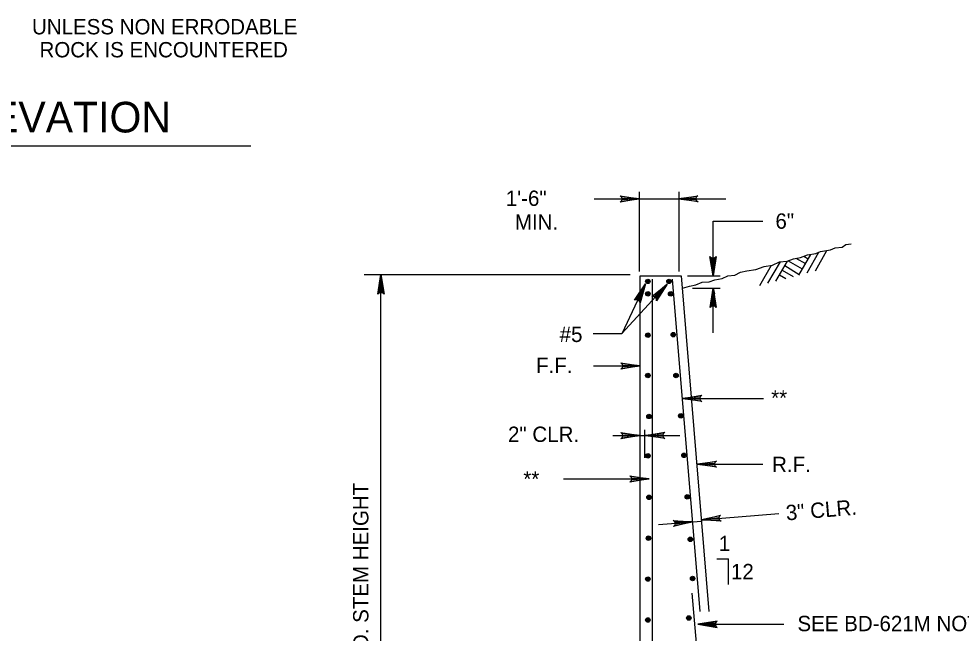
# Model space of a CAD drawing. Extents: x 639011 to 639866, y 298840 to 300028.
# Drawn here: x 639198.6 to 639383, y 299575.8 to 299696 of the extents above; entities that cross this region are included whole.
import ezdxf

# ---------------------------------------------------------------- set-up
doc = ezdxf.new("R2010")
doc.units = 0
doc.layers.add('2', color=7, linetype='Continuous')

msp = doc.modelspace()

# ---------------------------------------------------------------- linework, layer by layer
at = {"layer": '2'}
for p, q in [((639139.55, 299671.18), (639243.97, 299671.18)), ((639316.44, 299661.22), (639316.25, 299661.38)), ((639316.25, 299661.38), (639320.05, 299660.79)), ((639316.44, 299661.22), (639316.58, 299660.96)), ((639320.05, 299660.79), (639316.44, 299661.22)), ((639316.58, 299660.96), (639320.05, 299660.79)), ((639316.58, 299660.96), (639316.58, 299660.59)), ((639320.05, 299646.59), (639320.05, 299662.17)), ((639320.05, 299646.59), (639320.05, 299662.17)), ((639327.68, 299660.79), (639331.47, 299661.42)), ((639331.28, 299661.25), (639327.68, 299660.79)), ((639327.68, 299660.79), (639331.15, 299660.99)), ((639327.8, 299646.59), (639327.8, 299662.17)), ((639327.8, 299646.59), (639327.8, 299662.17)), ((639331.15, 299660.99), (639331.28, 299661.25)), ((639331.15, 299660.62), (639331.15, 299660.99)), ((639331.47, 299661.42), (639331.28, 299661.25)), ((639311.18, 299660.79), (639320.05, 299660.79)), ((639320.05, 299660.79), (639316.26, 299660.16)), ((639316.26, 299660.16), (639316.45, 299660.33)), ((639316.45, 299660.33), (639320.05, 299660.79)), ((639316.58, 299660.59), (639316.45, 299660.33)), ((639320.05, 299660.79), (639316.58, 299660.59)), ((639320.05, 299660.79), (639316.58, 299660.77)), ((639320.05, 299660.79), (639327.68, 299660.79)), ((639327.68, 299660.79), (639331.15, 299660.81)), ((639327.68, 299660.79), (639336.93, 299660.79)), ((639331.15, 299660.62), (639327.68, 299660.79)), ((639327.68, 299660.79), (639331.29, 299660.36)), ((639331.48, 299660.2), (639327.68, 299660.79)), ((639331.29, 299660.36), (639331.15, 299660.62)), ((639331.29, 299660.36), (639331.48, 299660.2)), ((639334.43, 299645.72), (639334.43, 299656.46)), ((639334.43, 299656.46), (639344.15, 299656.46)), ((639351.18, 299645.86), (639353.57, 299649.94)), ((639352.87, 299646.3), (639355.14, 299650.34)), ((639354.44, 299646.71), (639356.68, 299650.7)), ((639334.43, 299645.72), (639333.79, 299649.51)), ((639333.79, 299649.51), (639333.97, 299649.32)), ((639334.23, 299649.19), (639333.97, 299649.32)), ((639333.97, 299649.32), (639334.43, 299645.72)), ((639334.43, 299645.72), (639334.23, 299649.19)), ((639334.59, 299649.19), (639334.23, 299649.19)), ((639334.43, 299645.72), (639334.41, 299649.19)), ((639335.02, 299649.52), (639334.43, 299645.72)), ((639334.43, 299645.72), (639334.86, 299649.33)), ((639334.59, 299649.19), (639334.43, 299645.72)), ((639334.86, 299649.33), (639334.59, 299649.19)), ((639334.86, 299649.33), (639335.02, 299649.52)), ((639345.13, 299644.28), (639347.59, 299648.48)), ((639346.7, 299644.69), (639349.01, 299648.62)), ((639349.15, 299648.68), (639351.89, 299647.08)), ((639350.6, 299649.17), (639352.52, 299648.15)), ((639352.18, 299649.57), (639353.05, 299649.06)), ((639343.56, 299643.87), (639345.87, 299647.81)), ((639347.95, 299646.82), (639350.09, 299645.57)), ((639348.49, 299647.74), (639351.27, 299646.01)), ((639266.18, 299645.97), (639318.21, 299645.97)), ((639268.84, 299642.16), (639269.43, 299645.97)), ((639269.43, 299645.97), (639269, 299642.36)), ((639269.26, 299642.49), (639269.43, 299645.97)), ((639269.43, 299537.34), (639269.43, 299645.97)), ((639269.43, 299645.97), (639269.62, 299642.5)), ((639269.89, 299642.37), (639269.43, 299645.97)), ((639269.43, 299645.97), (639270.06, 299642.17)), ((639269.43, 299645.97), (639269.44, 299642.49)), ((639320.18, 299645.72), (639328.18, 299645.72)), ((639320.18, 299537.22), (639320.18, 299645.72)), ((639322.55, 299547.22), (639322.55, 299645.09)), ((639326.43, 299645.09), (639331.85, 299580.02)), ((639328.18, 299645.72), (639333.63, 299580)), ((639329.43, 299645.72), (639335.8, 299645.72)), ((639329.43, 299645.72), (639335.8, 299645.72)), ((639347.42, 299645.91), (639348.64, 299645.19)), ((639316.59, 299634.46), (639325.44, 299644.09)), ((639316.61, 299634.46), (639321.18, 299644.16)), ((639319.03, 299640.97), (639321.18, 299644.16)), ((639321.18, 299644.16), (639319.26, 299641.07)), ((639319.55, 299641.08), (639321.18, 299644.16)), ((639321.18, 299644.16), (639319.72, 299641.01)), ((639321.18, 299644.16), (639319.88, 299640.93)), ((639320.06, 299640.71), (639321.18, 299644.16)), ((639321.18, 299644.16), (639320.14, 299640.45)), ((639322.43, 299641.69), (639325.44, 299644.09)), ((639325.44, 299644.09), (639322.68, 299641.73)), ((639322.96, 299641.65), (639325.44, 299644.09)), ((639325.44, 299644.09), (639323.1, 299641.53)), ((639325.44, 299644.09), (639323.23, 299641.4)), ((639323.34, 299641.13), (639325.44, 299644.09)), ((639325.44, 299644.09), (639323.34, 299640.87)), ((639330.43, 299643.34), (639335.8, 299643.34)), ((639330.43, 299643.34), (639335.8, 299643.34)), ((639333.84, 299639.54), (639334.43, 299643.34)), ((639334.43, 299643.34), (639334, 299639.73)), ((639334.26, 299639.87), (639334.43, 299643.34)), ((639334.43, 299634.59), (639334.43, 299643.34)), ((639334.43, 299643.34), (639334.62, 299639.87)), ((639334.89, 299639.74), (639334.43, 299643.34)), ((639334.43, 299643.34), (639335.06, 299639.55)), ((639334.43, 299643.34), (639334.44, 299639.87)), ((639269, 299642.36), (639268.84, 299642.16)), ((639269, 299642.36), (639269.26, 299642.49)), ((639269.26, 299642.49), (639269.62, 299642.5)), ((639269.62, 299642.5), (639269.89, 299642.37)), ((639270.06, 299642.17), (639269.89, 299642.37)), ((639319.26, 299641.07), (639319.03, 299640.97)), ((639319.26, 299641.07), (639319.55, 299641.08)), ((639319.55, 299641.08), (639319.88, 299640.93)), ((639319.88, 299640.93), (639320.06, 299640.71)), ((639320.14, 299640.45), (639320.06, 299640.71)), ((639322.68, 299641.73), (639322.43, 299641.69)), ((639322.68, 299641.73), (639322.96, 299641.65)), ((639322.96, 299641.65), (639323.23, 299641.4)), ((639323.23, 299641.4), (639323.34, 299641.13)), ((639323.34, 299640.87), (639323.34, 299641.13)), ((639334, 299639.73), (639333.84, 299639.54)), ((639334, 299639.73), (639334.26, 299639.87)), ((639334.26, 299639.87), (639334.62, 299639.87)), ((639334.62, 299639.87), (639334.89, 299639.74)), ((639335.06, 299639.55), (639334.89, 299639.74)), ((639310.97, 299634.46), (639316.59, 299634.46)), ((639311.06, 299628.09), (639320.18, 299628.09)), ((639316.57, 299628.52), (639316.38, 299628.68)), ((639316.38, 299628.68), (639320.18, 299628.09)), ((639320.18, 299628.09), (639316.38, 299627.46)), ((639316.57, 299628.52), (639316.7, 299628.26)), ((639320.18, 299628.09), (639316.57, 299628.52)), ((639316.58, 299627.63), (639320.18, 299628.09)), ((639316.71, 299627.9), (639316.58, 299627.63)), ((639316.7, 299628.26), (639320.18, 299628.09)), ((639316.7, 299628.26), (639316.71, 299627.9)), ((639320.18, 299628.09), (639316.71, 299627.9)), ((639320.18, 299628.09), (639316.71, 299628.08)), ((639316.38, 299627.46), (639316.58, 299627.63)), ((639328.43, 299621.72), (639332.22, 299622.35)), ((639332.22, 299622.35), (639332.03, 299622.17)), ((639332.03, 299622.17), (639328.43, 299621.72)), ((639328.43, 299621.72), (639331.9, 299621.91)), ((639328.43, 299621.72), (639331.9, 299621.73)), ((639328.43, 299621.72), (639344.3, 299621.72)), ((639331.9, 299621.55), (639328.43, 299621.72)), ((639328.43, 299621.72), (639332.04, 299621.29)), ((639332.23, 299621.13), (639328.43, 299621.72)), ((639331.9, 299621.91), (639332.03, 299622.17)), ((639331.9, 299621.55), (639331.9, 299621.91)), ((639332.04, 299621.29), (639331.9, 299621.55)), ((639332.04, 299621.29), (639332.23, 299621.13)), ((639316.57, 299614.9), (639316.38, 299615.06)), ((639316.38, 299615.06), (639320.18, 299614.47)), ((639316.57, 299614.9), (639316.7, 299614.63)), ((639320.18, 299614.47), (639316.57, 299614.9)), ((639321.05, 299610.09), (639321.05, 299615.6)), ((639321.18, 299614.47), (639324.97, 299615.1)), ((639324.78, 299614.92), (639321.18, 299614.47)), ((639324.65, 299614.66), (639324.78, 299614.92)), ((639324.97, 299615.1), (639324.78, 299614.92)), ((639314.8, 299614.47), (639320.18, 299614.47)), ((639320.18, 299614.47), (639316.38, 299613.83)), ((639316.38, 299613.83), (639316.58, 299614.01)), ((639316.58, 299614.01), (639320.18, 299614.47)), ((639316.71, 299614.27), (639316.58, 299614.01)), ((639316.7, 299614.63), (639320.18, 299614.47)), ((639316.7, 299614.63), (639316.71, 299614.27)), ((639320.18, 299614.47), (639316.71, 299614.27)), ((639320.18, 299614.47), (639316.71, 299614.45)), ((639320.18, 299614.47), (639327.93, 299614.47)), ((639321.18, 299614.47), (639324.65, 299614.66)), ((639321.18, 299614.47), (639324.65, 299614.48)), ((639324.65, 299614.3), (639321.18, 299614.47)), ((639321.18, 299614.47), (639324.79, 299614.04)), ((639324.98, 299613.88), (639321.18, 299614.47)), ((639324.65, 299614.3), (639324.65, 299614.66)), ((639324.79, 299614.04), (639324.65, 299614.3)), ((639324.79, 299614.04), (639324.98, 299613.88)), ((639331.3, 299608.84), (639335.1, 299609.48)), ((639335.1, 299609.48), (639334.9, 299609.3)), ((639334.9, 299609.3), (639331.3, 299608.84)), ((639331.3, 299608.84), (639334.77, 299609.04)), ((639331.3, 299608.84), (639334.78, 299608.86)), ((639331.3, 299608.84), (639344.18, 299608.84)), ((639334.78, 299608.68), (639331.3, 299608.84)), ((639331.3, 299608.84), (639334.91, 299608.41)), ((639335.1, 299608.25), (639331.3, 299608.84)), ((639334.77, 299609.04), (639334.9, 299609.3)), ((639334.78, 299608.68), (639334.77, 299609.04)), ((639334.91, 299608.41), (639334.78, 299608.68)), ((639334.91, 299608.41), (639335.1, 299608.25)), ((639305.18, 299605.97), (639321.93, 299605.97)), ((639318.32, 299606.4), (639318.13, 299606.56)), ((639318.13, 299606.56), (639321.93, 299605.97)), ((639321.93, 299605.97), (639318.13, 299605.33)), ((639318.32, 299606.4), (639318.45, 299606.13)), ((639321.93, 299605.97), (639318.32, 299606.4)), ((639318.33, 299605.51), (639321.93, 299605.97)), ((639318.46, 299605.77), (639318.33, 299605.51)), ((639318.45, 299606.13), (639321.93, 299605.97)), ((639318.45, 299606.13), (639318.46, 299605.77)), ((639321.93, 299605.97), (639318.46, 299605.77)), ((639321.93, 299605.97), (639318.46, 299605.95)), ((639318.13, 299605.33), (639318.33, 299605.51)), ((639332.18, 299597.97), (639347.3, 299599.22)), ((639332.18, 299597.97), (639335.91, 299598.91)), ((639335.73, 299598.72), (639332.18, 299597.97)), ((639332.18, 299597.97), (639335.62, 299598.45)), ((639332.18, 299597.97), (639335.64, 299598.27)), ((639335.62, 299598.45), (639335.73, 299598.72)), ((639335.65, 299598.09), (639335.62, 299598.45)), ((639335.91, 299598.91), (639335.73, 299598.72)), ((639323.72, 299597.05), (639332.16, 299597.73)), ((639326.8, 299597.73), (639326.59, 299597.87)), ((639326.59, 299597.87), (639330.43, 299597.59)), ((639330.43, 299597.59), (639326.7, 299596.65)), ((639326.7, 299596.65), (639326.88, 299596.85)), ((639326.8, 299597.73), (639326.95, 299597.48)), ((639330.43, 299597.59), (639326.8, 299597.73)), ((639326.88, 299596.85), (639330.43, 299597.59)), ((639326.98, 299597.12), (639326.88, 299596.85)), ((639326.95, 299597.48), (639330.43, 299597.59)), ((639326.95, 299597.48), (639326.98, 299597.12)), ((639330.43, 299597.59), (639326.97, 299597.3)), ((639330.43, 299597.59), (639326.98, 299597.12)), ((639335.65, 299598.09), (639332.18, 299597.97)), ((639332.18, 299597.97), (639335.81, 299597.84)), ((639336.02, 299597.69), (639332.18, 299597.97)), ((639335.81, 299597.84), (639335.65, 299598.09)), ((639335.81, 299597.84), (639336.02, 299597.69)), ((639335.18, 299590.34), (639337.43, 299590.34)), ((639337.43, 299585.34), (639337.43, 299590.34)), ((639330.3, 299583.59), (639331.51, 299569.16)), ((639335.24, 299578.12), (639331.44, 299577.53)), ((639335.05, 299577.97), (639335.24, 299578.12)), ((639331.44, 299577.53), (639335.05, 299577.97)), ((639334.91, 299577.7), (639331.44, 299577.53)), ((639331.44, 299577.53), (639348.3, 299577.53)), ((639331.44, 299577.53), (639334.91, 299577.34)), ((639335.04, 299577.08), (639331.44, 299577.53)), ((639331.44, 299577.53), (639335.24, 299576.9)), ((639331.44, 299577.53), (639334.91, 299577.52)), ((639335.05, 299577.97), (639334.91, 299577.7)), ((639334.91, 299577.7), (639334.91, 299577.34)), ((639334.91, 299577.34), (639335.04, 299577.08)), ((639335.24, 299576.9), (639335.04, 299577.08))]:
    msp.add_line(p, q, dxfattribs=at)
for points in [[(639328.43, 299643.34), (639329.8, 299643.72), (639331.05, 299643.97), (639332.3, 299644.47), (639333.68, 299644.59), (639334.8, 299644.97), (639336.18, 299645.22), (639337.3, 299645.72), (639338.68, 299645.84), (639339.8, 299646.47), (639341.05, 299646.72), (639342.8, 299646.97), (639344.43, 299647.59), (639346.05, 299647.84), (639347.43, 299648.47), (639348.93, 299648.59), (639350.18, 299649.09), (639351.55, 299649.34), (639352.93, 299649.84), (639354.55, 299650.09), (639355.43, 299650.47), (639357.43, 299650.84), (639358.3, 299651.22), (639359.68, 299651.34), (639360.43, 299651.84), (639361.43, 299651.97)], [(639328.43, 299643.34), (639329.8, 299643.72), (639331.05, 299643.97), (639332.3, 299644.47), (639333.68, 299644.59), (639334.8, 299644.97), (639336.18, 299645.22), (639337.3, 299645.72), (639338.68, 299645.84), (639339.8, 299646.47), (639341.05, 299646.72), (639342.8, 299646.97), (639344.43, 299647.59), (639346.05, 299647.84), (639347.43, 299648.47), (639348.93, 299648.59), (639350.18, 299649.09), (639351.55, 299649.34), (639352.93, 299649.84), (639354.55, 299650.09), (639355.43, 299650.47), (639357.43, 299650.84), (639358.3, 299651.22), (639359.68, 299651.34), (639360.43, 299651.84), (639361.43, 299651.97)], [(639334.3, 299642.22), (639334.43, 299642.22), (639334.43, 299643.34), (639334.3, 299642.22), (639334.3, 299642.22), (639334.43, 299643.34), (639334.55, 299642.22), (639334.55, 299642.22), (639334.43, 299643.34), (639334.68, 299642.22), (639334.55, 299642.22)]]:
    msp.add_lwpolyline(points, dxfattribs=at)
for centre, radius in [((639321.67, 299644.64), 0.437), ((639321.67, 299644.64), 0.437), ((639321.67, 299644.64), 0.312), ((639321.67, 299644.64), 0.312), ((639321.67, 299644.64), 0.17), ((639321.67, 299644.64), 0.17), ((639321.67, 299644.64), 0.086), ((639321.67, 299644.64), 0.086), ((639321.67, 299644.64), 0.0368), ((639321.67, 299644.64), 0.0368), ((639325.81, 299644.64), 0.437), ((639325.81, 299644.64), 0.437), ((639325.81, 299644.64), 0.312), ((639325.81, 299644.64), 0.312), ((639325.81, 299644.64), 0.17), ((639325.81, 299644.64), 0.17), ((639325.81, 299644.64), 0.086), ((639325.81, 299644.64), 0.086), ((639325.81, 299644.64), 0.0368), ((639325.81, 299644.64), 0.0368), ((639321.67, 299642.22), 0.437), ((639321.67, 299642.22), 0.437), ((639321.67, 299642.22), 0.312), ((639321.67, 299642.22), 0.312), ((639326.14, 299642.22), 0.437), ((639326.14, 299642.22), 0.437), ((639326.14, 299642.22), 0.312), ((639326.14, 299642.22), 0.312), ((639321.67, 299642.22), 0.17), ((639321.67, 299642.22), 0.17), ((639321.67, 299642.22), 0.086), ((639321.67, 299642.22), 0.086), ((639321.67, 299642.22), 0.0368), ((639321.67, 299642.22), 0.0368), ((639326.14, 299642.22), 0.17), ((639326.14, 299642.22), 0.17), ((639326.14, 299642.22), 0.086), ((639326.14, 299642.22), 0.086), ((639326.14, 299642.22), 0.0368), ((639326.14, 299642.22), 0.0368), ((639321.67, 299634.11), 0.437), ((639321.67, 299634.11), 0.437), ((639321.67, 299634.11), 0.312), ((639321.67, 299634.11), 0.312), ((639321.67, 299634.11), 0.17), ((639321.67, 299634.11), 0.17), ((639321.67, 299634.11), 0.086), ((639321.67, 299634.11), 0.086), ((639321.67, 299634.11), 0.0368), ((639321.67, 299634.11), 0.0368), ((639326.64, 299634.22), 0.437), ((639326.64, 299634.22), 0.437), ((639326.64, 299634.22), 0.312), ((639326.64, 299634.22), 0.312), ((639326.64, 299634.22), 0.17), ((639326.64, 299634.22), 0.17), ((639326.64, 299634.22), 0.086), ((639326.64, 299634.22), 0.086), ((639326.64, 299634.22), 0.0368), ((639326.64, 299634.22), 0.0368), ((639321.67, 299626.22), 0.437), ((639321.67, 299626.22), 0.437), ((639321.67, 299626.22), 0.312), ((639321.67, 299626.22), 0.312), ((639321.67, 299626.22), 0.17), ((639321.67, 299626.22), 0.17), ((639321.67, 299626.22), 0.086), ((639321.67, 299626.22), 0.086), ((639321.67, 299626.22), 0.0368), ((639321.67, 299626.22), 0.0368), ((639327.18, 299626.22), 0.437), ((639327.18, 299626.22), 0.437), ((639327.18, 299626.22), 0.312), ((639327.18, 299626.22), 0.312), ((639327.18, 299626.22), 0.17), ((639327.18, 299626.22), 0.17), ((639327.18, 299626.22), 0.086), ((639327.18, 299626.22), 0.086), ((639327.18, 299626.22), 0.0368), ((639327.18, 299626.22), 0.0368), ((639321.89, 299618.21), 0.437), ((639321.89, 299618.21), 0.437), ((639328.12, 299618.32), 0.437), ((639328.12, 299618.32), 0.437), ((639328.12, 299618.32), 0.312), ((639328.12, 299618.32), 0.312), ((639321.89, 299618.21), 0.312), ((639321.89, 299618.21), 0.312), ((639321.89, 299618.21), 0.17), ((639321.89, 299618.21), 0.17), ((639321.89, 299618.21), 0.086), ((639321.89, 299618.21), 0.086), ((639321.89, 299618.21), 0.0368), ((639321.89, 299618.21), 0.0368), ((639328.12, 299618.32), 0.17), ((639328.12, 299618.32), 0.17), ((639328.12, 299618.32), 0.086), ((639328.12, 299618.32), 0.086), ((639328.12, 299618.32), 0.0368), ((639328.12, 299618.32), 0.0368), ((639321.67, 299610.49), 0.437), ((639321.67, 299610.49), 0.437), ((639321.67, 299610.49), 0.312), ((639321.67, 299610.49), 0.312), ((639321.67, 299610.49), 0.17), ((639321.67, 299610.49), 0.17), ((639321.67, 299610.49), 0.086), ((639321.67, 299610.49), 0.086), ((639321.67, 299610.49), 0.0368), ((639321.67, 299610.49), 0.0368), ((639328.72, 299610.59), 0.437), ((639328.72, 299610.59), 0.437), ((639328.72, 299610.59), 0.312), ((639328.72, 299610.59), 0.312), ((639328.72, 299610.59), 0.17), ((639328.72, 299610.59), 0.17), ((639328.72, 299610.59), 0.086), ((639328.72, 299610.59), 0.086), ((639328.72, 299610.59), 0.0368), ((639328.72, 299610.59), 0.0368), ((639321.89, 299602.37), 0.437), ((639321.89, 299602.37), 0.437), ((639321.89, 299602.37), 0.312), ((639321.89, 299602.37), 0.312), ((639321.89, 299602.37), 0.17), ((639321.89, 299602.37), 0.17), ((639321.89, 299602.37), 0.086), ((639321.89, 299602.37), 0.086), ((639321.89, 299602.37), 0.0368), ((639321.89, 299602.37), 0.0368), ((639329.38, 299602.48), 0.437), ((639329.38, 299602.48), 0.437), ((639329.38, 299602.48), 0.312), ((639329.38, 299602.48), 0.312), ((639329.38, 299602.48), 0.17), ((639329.38, 299602.48), 0.17), ((639329.38, 299602.48), 0.086), ((639329.38, 299602.48), 0.086), ((639329.38, 299602.48), 0.0368), ((639329.38, 299602.48), 0.0368), ((639321.78, 299594.37), 0.437), ((639321.78, 299594.37), 0.437), ((639321.78, 299594.37), 0.312), ((639321.78, 299594.37), 0.312), ((639329.98, 299594.15), 0.437), ((639329.98, 299594.15), 0.437), ((639321.78, 299594.37), 0.17), ((639321.78, 299594.37), 0.17), ((639321.78, 299594.37), 0.086), ((639321.78, 299594.37), 0.086), ((639321.78, 299594.37), 0.0368), ((639321.78, 299594.37), 0.0368), ((639329.98, 299594.15), 0.312), ((639329.98, 299594.15), 0.312), ((639329.98, 299594.15), 0.17), ((639329.98, 299594.15), 0.17), ((639329.98, 299594.15), 0.086), ((639329.98, 299594.15), 0.086), ((639329.98, 299594.15), 0.0368), ((639329.98, 299594.15), 0.0368), ((639321.67, 299586.37), 0.437), ((639321.67, 299586.37), 0.437), ((639321.67, 299586.37), 0.312), ((639321.67, 299586.37), 0.312), ((639321.67, 299586.37), 0.17), ((639321.67, 299586.37), 0.17), ((639321.67, 299586.37), 0.086), ((639321.67, 299586.37), 0.086), ((639321.67, 299586.37), 0.0368), ((639321.67, 299586.37), 0.0368), ((639330.42, 299586.48), 0.437), ((639330.42, 299586.48), 0.437), ((639330.42, 299586.48), 0.312), ((639330.42, 299586.48), 0.312), ((639330.42, 299586.48), 0.17), ((639330.42, 299586.48), 0.17), ((639330.42, 299586.48), 0.086), ((639330.42, 299586.48), 0.086), ((639330.42, 299586.48), 0.0368), ((639330.42, 299586.48), 0.0368), ((639321.67, 299578.36), 0.437), ((639321.67, 299578.36), 0.437), ((639321.67, 299578.36), 0.312), ((639321.67, 299578.36), 0.312), ((639321.67, 299578.36), 0.17), ((639321.67, 299578.36), 0.17), ((639321.67, 299578.36), 0.086), ((639321.67, 299578.36), 0.086), ((639321.67, 299578.36), 0.0368), ((639321.67, 299578.36), 0.0368), ((639329.69, 299578.75), 0.437), ((639329.69, 299578.75), 0.437), ((639329.69, 299578.75), 0.312), ((639329.69, 299578.75), 0.312), ((639329.69, 299578.75), 0.17), ((639329.69, 299578.75), 0.17), ((639329.69, 299578.75), 0.086), ((639329.69, 299578.75), 0.086), ((639329.69, 299578.75), 0.0368), ((639329.69, 299578.75), 0.0368)]:
    msp.add_circle(centre, radius, dxfattribs=at)

# ---------------------------------------------------------------- texts
for s, height, p in [('UNLESS NON ERRODABLE', 3, (639201.16, 299693)), ('ROCK IS ENCOUNTERED', 3, (639202.64, 299688.5)), ('ENDWALL ELEVATION', 6, (639142.31, 299673.8)), ('1\'-6"', 3, (639293.88, 299659.42)), ('MIN.', 3, (639295.65, 299654.74)), ('6"', 3, (639346.63, 299654.95)), ('#5', 3, (639304.41, 299632.78)), ('F.F.', 3, (639299.79, 299626.69)), ('**', 3, (639345.8, 299620.34)), ('2" CLR.', 3, (639294.3, 299613.22)), ('**', 3, (639297.3, 299604.47)), ('1', 3, (639335.55, 299591.84)), ('12', 3, (639337.93, 299586.34)), ('SEE BD-621M NOTES 11 AND 13.', 3, (639350.94, 299576.17))]:
    msp.add_text(s, height=height, dxfattribs=at).set_placement(p)
for s, rotation, p in [('R.F.', 0.0251, (639345.98, 299607.31)), ("REQ'D. STEM HEIGHT", 90, (639266.99, 299563.22)), ('3" CLR.', 4.7481, (639348.8, 299597.84))]:
    msp.add_text(s, height=3, rotation=rotation, dxfattribs=at).set_placement(p)

doc.saveas('drawing.dxf')
